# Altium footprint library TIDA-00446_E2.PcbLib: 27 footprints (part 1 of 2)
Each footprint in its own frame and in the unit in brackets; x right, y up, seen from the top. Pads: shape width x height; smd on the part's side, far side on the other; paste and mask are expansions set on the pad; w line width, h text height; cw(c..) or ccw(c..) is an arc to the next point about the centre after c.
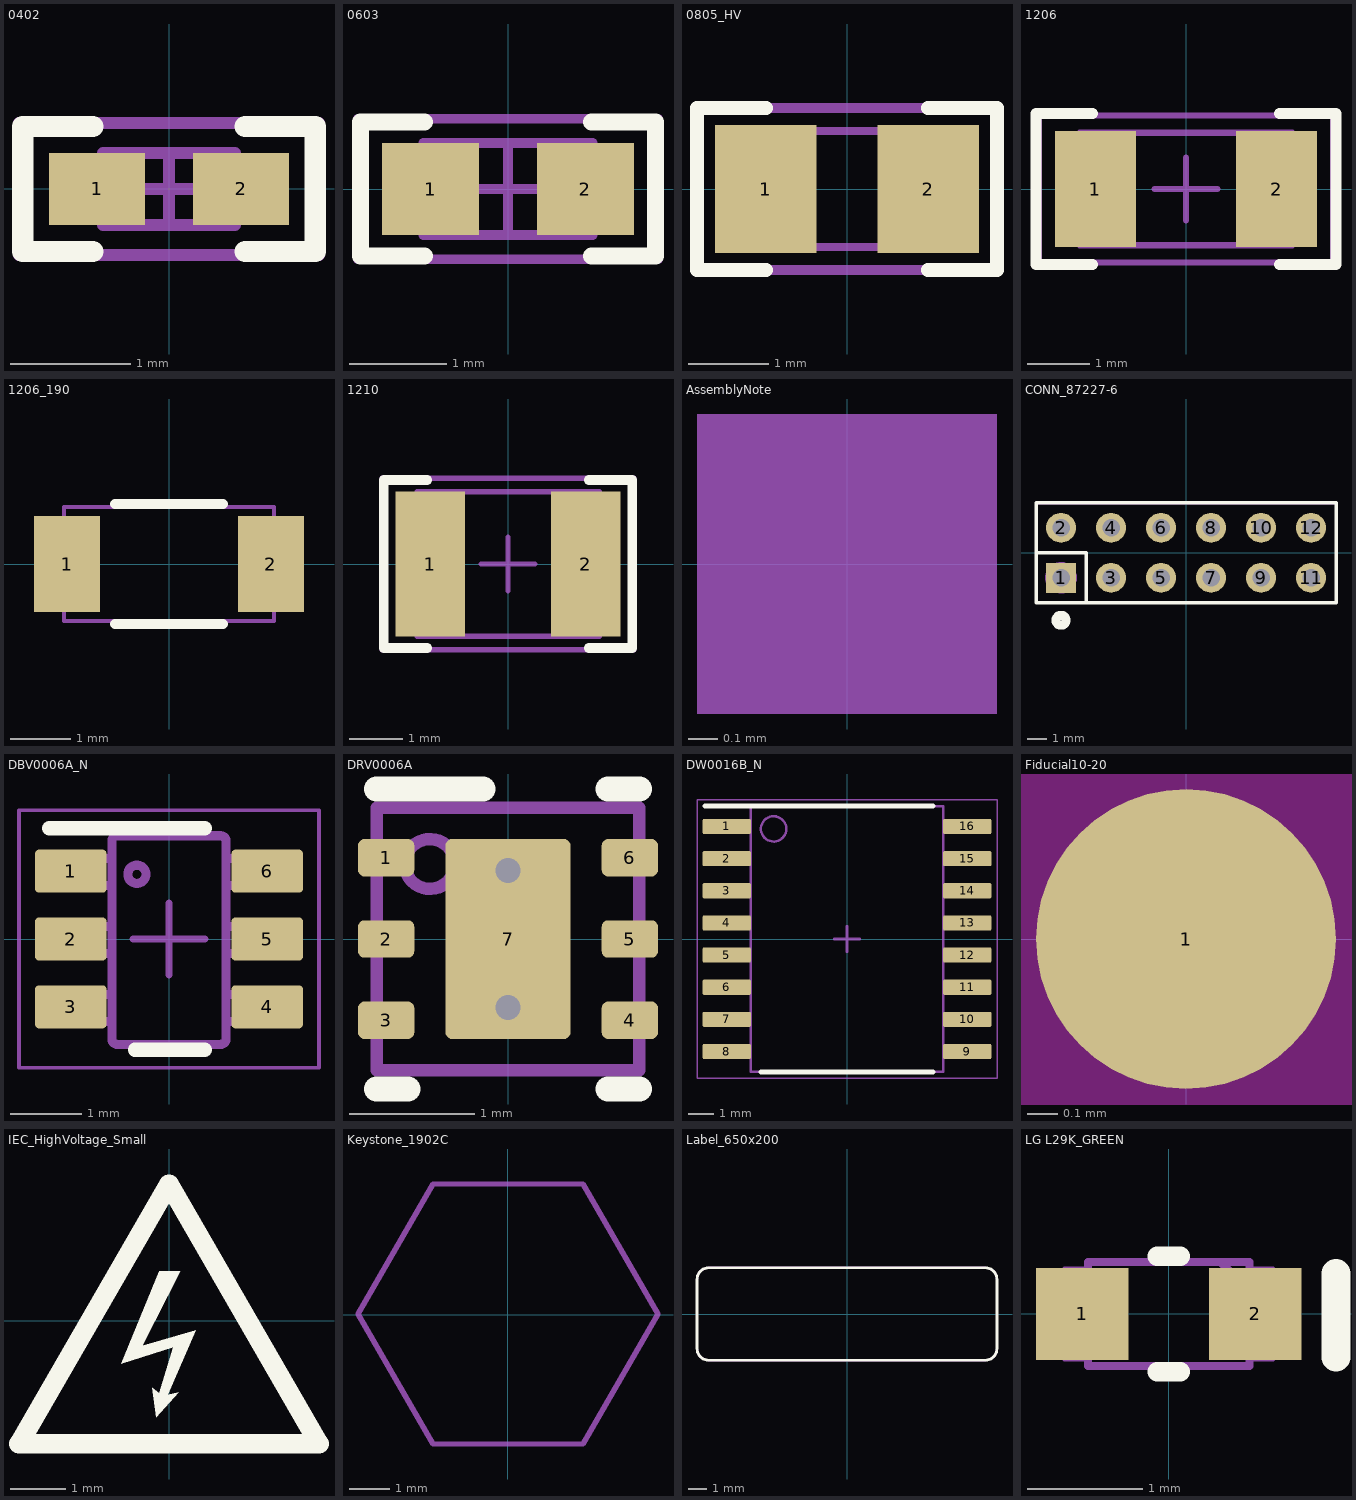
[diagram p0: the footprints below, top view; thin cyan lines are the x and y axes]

## 0402 [mm] "0402 from SM-752 data"
height 0.6
pads (2):
  rect 0.8x0.6 smd: 1(-0.6,0) 2(0.6,0)
Top Overlay:
  lines w0.178: -0.635,-0.521 -1.219,-0.521 -1.219,0.521 -0.635,0.521 ; 0.635,-0.521 1.219,-0.521 1.219,0.521 0.635,0.521
Mechanical 5:
  lines w0.1: -1.25,-0.55 -1.25,0.55 1.25,0.55 1.25,-0.55 -1.25,-0.55
  text ".Designator" at 1.537,-0.394 h0.76
Mechanical 13:
  lines w0.1: -0.35,-0.3 -0.35,0.3 ; 0.35,-0.3 0.35,0.3 ; -0.55,-0.3 0.55,-0.3 0.55,0.3 -0.55,0.3 -0.55,-0.3
Mechanical 15:
  lines w0.1: -0.3,0 0.3,0 ; 0,-0.3 0,0.3 ; -1.25,-0.55 1.25,-0.55 1.25,0.55 -1.25,0.55 -1.25,-0.55
3D body: height 0.6, standoff 0, extent 0.351,-0.299 0.549,0.299
3D body: height 0.6, standoff 0, extent -0.349,-0.299 0.349,0.299
3D body: height 0.6, standoff 0, extent -0.549,-0.299 -0.351,0.299

## 0603 [mm] "0603 from SM-752 data"
height 0.85
pads (2):
  rect 1x0.95 smd: 1(-0.8,0) 2(0.8,0)
Top Overlay:
  lines w0.178: -0.864,-0.691 -1.524,-0.691 -1.524,0.693 -0.864,0.693 ; 0.864,-0.691 1.524,-0.691 1.524,0.693 0.864,0.693
Mechanical 5:
  lines w0.1: -1.55,-0.725 -1.55,0.725 1.55,0.725 1.55,-0.725 -1.55,-0.725
  text ".Designator" at -0.94,-0.381 h0.76
Mechanical 13:
  lines w0.1: -0.55,-0.475 -0.55,0.475 ; 0.55,-0.475 0.55,0.475 ; -0.875,-0.475 0.875,-0.475 0.875,0.475 -0.875,0.475 -0.875,-0.475
Mechanical 15:
  lines w0.1: -0.475,0 0.475,0 ; 0,-0.475 0,0.475 ; -1.55,-0.725 1.55,-0.725 1.55,0.725 -1.55,0.725 -1.55,-0.725
3D body: height 0.85, standoff 0, extent -0.874,-0.474 -0.551,0.474
3D body: height 0.85, standoff 0, extent -0.549,-0.474 0.549,0.474
3D body: height 0.85, standoff 0, extent 0.551,-0.474 0.874,0.474

## 0805_HV [mil] "0805 with 30mil clearance between pads"
height 57.09
pads (2):
  rect 50x63 smd: 1(-40,0) 2(40,0)
Top Overlay:
  lines w7: -40,-40 -74,-40 -74,0 -74,40 -40,40 ; 40,-40 74,-40 74,0 74,40 40,40
Mechanical 5:
  lines w5: -74,-40 74,-40 74,40 -74,40 -74,-40
  text ".Designator" at -30.51,-14.49 h30
Mechanical 13:
  lines w3.94: -25.59,-28.54 -25.59,28.54 ; 25.59,-28.54 25.59,28.54 ; -43.31,-28.54 43.31,-28.54 43.31,28.54 -43.31,28.54 -43.31,-28.54
3D body: height 57.09, standoff 0, extent -43.29,-28.52 -25.61,28.52
3D body: height 57.09, standoff 0, extent -25.57,-28.52 25.57,28.52
3D body: height 57.09, standoff 0, extent 25.61,-28.52 43.29,28.52

## 1206 [mm] "1206 from SM-752 data"
height 1.35
pads (2):
  rect 1.3x1.85 smd: 1(-1.45,0) 2(1.45,0)
Top Overlay:
  lines w0.178: -1.5,-1.21 -2.4,-1.21 -2.4,1.21 -1.5,1.21 ; 1.5,-1.21 2.4,-1.21 2.4,1.21 1.5,1.21
Mechanical 5:
  lines w0.1: -1.7,-0.9 1.7,-0.9 1.7,0.9 -1.7,0.9 -1.7,-0.9
  text ".Designator" at 0.699,0.317 h0.76
Mechanical 13:
  lines w0.1: -1.2,-0.9 -1.2,0.9 ; 1.2,-0.9 1.2,0.9 ; -1.7,-0.9 1.7,-0.9 1.7,0.9 -1.7,0.9 -1.7,-0.9
Mechanical 15:
  lines w0.1: -0.5,0 0.5,0 ; 0,-0.5 0,0.5 ; -2.35,-1.175 2.35,-1.175 2.35,1.175 -2.35,1.175 -2.35,-1.175
3D body: height 1.35, standoff 0, extent -1.699,-0.899 -1.201,0.899
3D body: height 1.35, standoff 0, extent -1.199,-0.899 1.199,0.899
3D body: height 1.35, standoff 0, extent 1.201,-0.899 1.699,0.899

## 1206_190 [mm] "1206_190"
height 1.9
pads (2):
  rect 1.1x1.6 smd: 1(-1.7,0) 2(1.7,0)
Top Overlay:
  lines w0.17: -0.9,-1 0.9,-1 ; -0.9,1 0.9,1
Mechanical 5:
  lines w0.07: -1.75,-0.95 -1.75,0.95 1.75,0.95 1.75,-0.95 -1.75,-0.95
  text ".Designator" at 0.927,0.343 h0.76
3D body: height 1.9, standoff 0, extent 1.301,-0.949 1.749,0.949
3D body: height 1.9, standoff 0, extent -1.299,-0.949 1.299,0.949
3D body: height 1.9, standoff 0, extent -1.749,-0.949 -1.301,0.949

## 1210 [mm] "1210 from SM-752 data"
height 1.35
pads (2):
  rect 1.3x2.7 smd: 1(-1.45,0) 2(1.45,0)
Top Overlay:
  lines w0.178: -1.511,-1.568 -2.316,-1.568 -2.316,1.568 -1.511,1.568 ; 1.511,-1.568 2.316,-1.568 2.316,1.568 1.511,1.568
Mechanical 5:
  lines w0.1: -1.7,-1.35 -1.7,1.35 1.7,1.35 1.7,-1.35 -1.7,-1.35
  text ".Designator" at 0.838,0.381 h0.76
Mechanical 13:
  lines w0.1: -1.2,-1.35 -1.2,1.35 ; 1.2,-1.35 1.2,1.35 ; -1.7,-1.35 1.7,-1.35 1.7,1.35 -1.7,1.35 -1.7,-1.35
Mechanical 15:
  lines w0.1: -0.5,0 0.5,0 ; 0,-0.5 0,0.5 ; -2.35,-1.6 2.35,-1.6 2.35,1.6 -2.35,1.6 -2.35,-1.6
3D body: height 1.35, standoff 0, extent 1.201,-1.349 1.699,1.349
3D body: height 1.35, standoff 0, extent -1.199,-1.349 1.199,1.349
3D body: height 1.35, standoff 0, extent -1.699,-1.349 -1.201,1.349

## AssemblyNote [mm] "Assembly Note"
Mechanical 5:
  rectangle: -0.508,-0.508 0.508,0.508
  text ".Designator" at -4.191,-0.508 h0.76
  text ".Comment" at 1.143,-0.508 h0.76

## CONN_87227-6 [mil] "TE Connectivity"
height 408
pads (12):
  rect 60x60 hole 35: 1(-250,-50)
  round 60 hole 35: 2(-250,50) 3(-150,-50) 4(-150,50) 5(-50,-50) 6(-50,50) 7(50,-50) 8(50,50) 9(150,-50) 10(150,50) 11(250,-50) 12(250,50)
Top Overlay:
  circle w18: c-250,-135 r10
  lines w7: -300,0 -200,0 -200,-100 ; -300,-100 -300,100 300,100 300,-100 -300,-100
Mechanical 5:
  circle w4: c-250,-50 r30
  lines w4: -300,-99 300,-99 300,99 -300,99 -300,-99
  text ".Designator" at -19,-13 h30
3D body: height 408, standoff -137, extent 238,-62 262,-38
3D body: height 408, standoff -137, extent 238,38 262,62
3D body: height 408, standoff -137, extent 138,-62 162,-38
3D body: height 408, standoff -137, extent 138,38 162,62
3D body: height 408, standoff -137, extent 38,-62 62,-38
3D body: height 408, standoff -137, extent 38,38 62,62
3D body: height 408, standoff -137, extent -62,-62 -38,-38
3D body: height 408, standoff -137, extent -62,38 -38,62
3D body: height 408, standoff -137, extent -162,-62 -138,-38
3D body: height 408, standoff -137, extent -162,38 -138,62
3D body: height 408, standoff -137, extent -262,-62 -238,-38
3D body: height 408, standoff -137, extent -262,38 -238,62
3D body: height 80, standoff 0, extent -299.98,-98.98 299.98,98.98

## DBV0006A_N [mm] "SOT23, 6-Leads, Body 2.9x1.6mm, Pitch 0.95mm, Lead Span 2.8mm, IPC Medium Density"
height 1.45
pads (6):
  rrect17% 1x0.6 smd: 1(-1.375,0.95) 2(-1.375,0) 3(-1.375,-0.95) 4(1.375,-0.95) 5(1.375,0) 6(1.375,0.95)
Top Overlay:
  lines w0.2: -1.675,1.55 0.5,1.55 ; -0.475,-1.55 0.5,-1.55
Mechanical 5:
  lines w0.127: 0.724,-1.475 ccw(c0.723,-1.399) 0.8,-1.399 0.8,1.37 ccw(c0.723,1.37) 0.724,1.446 ; 0.723,-1.475 0.724,-1.475 ; 0.723,-1.475 -0.724,-1.475 -0.725,-1.475 cw(c-0.724,-1.399) -0.801,-1.399 -0.801,1.37 cw(c-0.724,1.37) -0.725,1.446 -0.724,1.446 0.723,1.446 ; 0.723,1.446 0.724,1.446 ; -1.423,-1.154 -1.206,-1.154 -1.113,-1.154 -1.081,-1.154 -0.828,-1.154 -0.801,-1.154 -0.801,-0.78 -0.828,-0.78 -1.081,-0.78 -1.113,-0.78 -1.206,-0.78 -1.423,-0.78 -1.423,-1.154 ; -1.423,-0.202 -1.206,-0.202 -1.113,-0.202 -1.081,-0.202 -0.828,-0.202 -0.801,-0.202 -0.801,0.173 -0.828,0.173 -1.081,0.173 -1.113,0.173 -1.206,0.173 -1.423,0.173 -1.423,-0.202 ; -1.423,0.751 -1.206,0.751 -1.113,0.751 -1.081,0.751 -0.828,0.751 -0.801,0.751 -0.801,1.125 -0.828,1.125 -1.081,1.125 -1.113,1.125 -1.206,1.125 -1.423,1.125 -1.423,0.751 ; -0.577,0.906 cw(c-0.45,0.906) -0.323,0.906 cw(c-0.45,0.906) -0.577,0.906 ; 0.8,-1.154 0.827,-1.154 1.08,-1.154 1.112,-1.154 1.205,-1.154 1.422,-1.154 1.422,-0.78 1.205,-0.78 1.112,-0.78 1.08,-0.78 0.827,-0.78 0.8,-0.78 0.8,-1.154 ; 0.8,-0.202 0.827,-0.202 1.08,-0.202 1.112,-0.202 1.205,-0.202 1.422,-0.202 1.422,0.173 1.205,0.173 1.112,0.173 1.08,0.173 0.827,0.173 0.8,0.173 0.8,-0.202 ; 0.8,0.751 0.827,0.751 1.08,0.751 1.112,0.751 1.205,0.751 1.422,0.751 1.422,1.125 1.205,1.125 1.112,1.125 1.08,1.125 0.827,1.125 0.8,1.125 0.8,0.751
  text ".Designator" at -0.267,0.445 h0.76
Mechanical 15:
  lines w0.05: -2.1,-1.8 2.1,-1.8 2.1,1.8 -2.1,1.8 -2.1,-1.8
  lines w0.1: -0.5,0 0.5,0 ; 0,-0.5 0,0.5
3D body: height 1.12, standoff 0, extent -1.422,-1.461 1.423,1.46

## DRV0006A [mm] "SON, 6-Leads, Body 2x2mm, Pitch 0.65mm, Thermal Pad 1.6x1mm, TI Recommended"
height 0.8
pads (7):
  rrect33% 0.45x0.3 smd: 1(-0.975,0.65) 2(-0.975,0) 3(-0.975,-0.65) 4(0.975,-0.65) 5(0.975,0) 6(0.975,0.65)
  rrect10% 1x1.6 smd paste-0.5: 7(0,0)
via 0,0.55 diameter 0.5 hole 0.2
via 0,-0.55 diameter 0.5 hole 0.2
Top Overlay:
  lines w0.2: -1.05,-1.2 -0.8,-1.2 ; -1.05,1.2 -0.2,1.2 ; 0.8,-1.2 1.05,-1.2 ; 0.8,1.2 1.05,1.2
Top Paste:
  region: 0.475,-0.733 0.475,0.733 -0.474,0.733 -0.474,-0.733
Mechanical 5:
  circle w0.1: c-0.625,0.6 r0.2
  lines w0.1: -1.05,-1.05 -1.05,1.05 1.05,1.05 1.05,-1.05 -1.05,-1.05
  text ".Designator" at -0.9,-0.5 h0.76
3D body: height 0.8, standoff 0, extent -1.05,-1.05 1.05,1.05
3D body: height 0.81, standoff 0.5, extent -0.828,0.397 -0.422,0.803

## DW0016B_N [mm] "SOIC, 16-Leads, Body 10.5x7.6mm, Pitch 1.27mm, IPC Medium Density"
height 2.65
pads (16):
  rrect17% 1.9x0.6 smd: 1(-4.75,4.445) 2(-4.75,3.175) 3(-4.75,1.905) 4(-4.75,0.635) 5(-4.75,-0.635) 6(-4.75,-1.905) 7(-4.75,-3.175) 8(-4.75,-4.445) 9(4.75,-4.445) 10(4.75,-3.175) 11(4.75,-1.905) 12(4.75,-0.635) 13(4.75,0.635) 14(4.75,1.905) 15(4.75,3.175) 16(4.75,4.445)
Top Overlay:
  lines w0.2: -5.6,5.25 3.4,5.25 ; -3.4,-5.25 3.4,-5.25
Mechanical 5:
  text ".Designator" at -2.274,0.012 h0.76
Mechanical 13:
  circle w0.1: c-2.9,4.35 r0.5
  lines w0.1: -3.8,-5.25 3.8,-5.25 3.8,5.25 -3.8,5.25 -3.8,-5.25
Mechanical 15:
  lines w0.05: -5.925,-5.5 5.925,-5.5 5.925,5.5 -5.925,5.5 -5.925,-5.5
  lines w0.1: -0.5,0 0.5,0 ; 0,-0.5 0,0.5
3D body: height 2.59, standoff 0, extent -5.167,-5.15 5.168,5.15

## Fiducial10-20 [mm]
pads (1):
  round 1 smd mask+0.5: 1(0,0)
Top Layer keep-out:
  circle w1.178: c0,0 r0.5

## IEC_HighVoltage_Small [mm]
height 0.6
Top Overlay:
  region: -0.178,0.889 0.203,0.889 -0.483,-0.457 0.483,-0.178 -0.025,-1.346 0.178,-1.295 -0.229,-1.753 -0.305,-1.219 -0.178,-1.321 0.076,-0.483 -0.864,-0.787
  lines w0.356: -2.718,-2.235 2.718,-2.235 0,2.472 -2.718,-2.235

## Keystone_1902C [mil] "Hex Standoff, 4-40 threaded, nylon"
height 500
pads (1):
  round 1 on Mech3: 0(0,0)
Mechanical 5:
  lines w5: -145.29,0.49 -72.56,126.47 72.92,126.47 145.65,0.49 72.92,-125.49 -72.56,-125.49 -145.29,0.49
  text ".Designator" at -28,-15 h30
3D body: height 501, standoff 1, extent -144.95,-125.98 146,125.98

## Label_650x200 [mil] "Thermal Transfer Label"
height 1
pads (1):
  round 1 on Mech13: 0(0,0)
Top Overlay:
  lines w6: -325,-75 ccw(c-300,-75) -300,-100 300,-100 ccw(c300,-75) 325,-75 325,75 ccw(c300,75) 300,100 -300,100 ccw(c-300,75) -325,75 -325,-75
Mechanical 5:
  lines w5: -325,-75 ccw(c-300,-75) -300,-100 300,-100 ccw(c300,-75) 325,-75 325,75 ccw(c300,75) 300,100 -300,100 ccw(c-300,75) -325,75 -325,-75
  text ".Designator" at -60,-20 h30
3D body: height 1, standoff 0, extent -325.51,-100.51 325.51,100.51

## LG L29K_GREEN [mm] "OSRAM"
height 0.67
pads (2):
  rect 0.8x0.8 smd paste-0.4: 1(-0.75,0) 2(0.75,0)
Top Overlay:
  lines w0.17: -0.1,-0.5 0.1,-0.5 ; -0.1,0.5 0.1,0.5
  lines w0.25: 1.45,-0.375 1.45,0.35
Top Paste:
  rectangle: -1.1,-0.35 -0.5,0.35
  rectangle: 0.5,-0.35 1.1,0.35
Mechanical 5:
  lines w0.07: 0.7,0.375 0.9,0.375 0.9,-0.375 0.7,-0.375 ; 0.7,-0.375 0.7,0.2 ; 0.7,-0.375 0.7,-0.45 -0.7,-0.45 -0.7,-0.375 -0.9,-0.375 -0.9,0.375 -0.7,0.375 -0.7,0.45 0.7,0.45 ; 0.7,0.2 0.45,0.45 0.7,0.45 ; 0.7,0.2 0.7,0.45
  text ".Designator" at 0.825,1.512 h0.76
3D body: height 0.18, standoff 0, extent -0.899,-0.374 -0.701,0.374
3D body: height 0.18, standoff 0, extent 0.701,-0.374 0.899,0.374
3D body: height 0.18, standoff 0, extent -0.699,-0.449 0.699,0.449
3D body: height 0.67, standoff 0.18, extent -0.699,-0.449 0.699,0.449
3D body: height 0.67, standoff 0.65, extent 0.451,0.201 0.699,0.449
